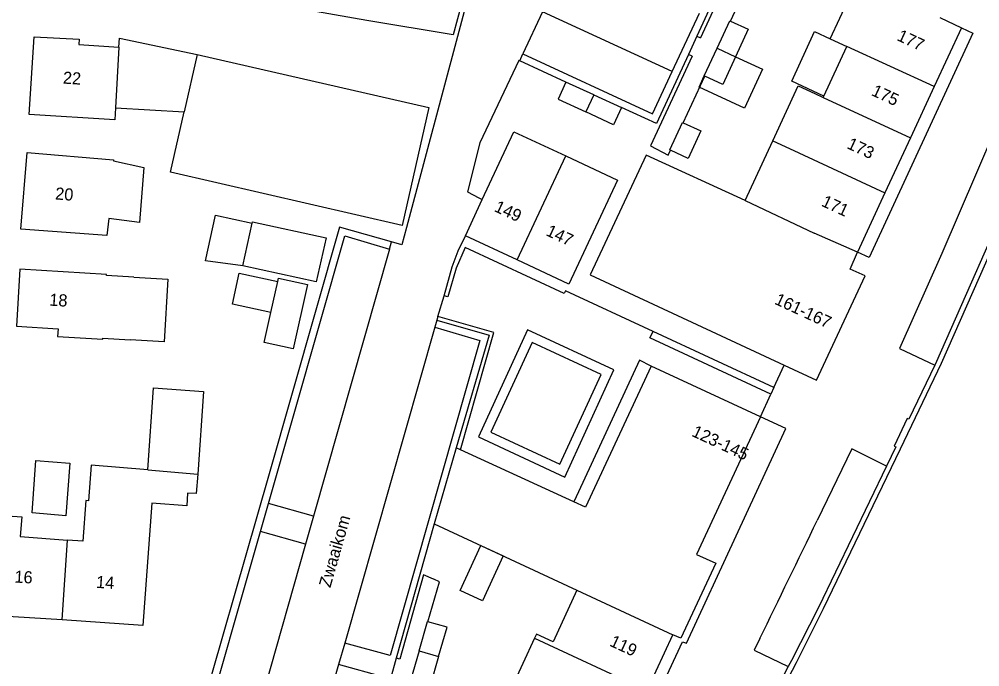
# Model space of a CAD drawing. Extents: x 194485 to 197793, y 468269 to 470822.
# Drawn here: x 194851.3 to 194946.2, y 470211.6 to 470275.6 of the extents above; entities that cross this region are included whole.
import ezdxf

# ---------------------------------------------------------------- set-up
doc = ezdxf.new("R2010")
doc.units = 0
for name, color, linetype in [('BGT grensvlak gebouwinstallatie plus 1', 7, 'Continuous'), ('BGT grensvlak pand op maaiveld', 7, 'Continuous'), ('BGT grensvlak pand op maaiveld LR', 7, 'Continuous'), ('BGT grensvlak scheiding', 7, 'Continuous'), ('BGT grensvlak wegdeel', 7, 'Continuous'), ('BGT tekst huisnummerreeks', 7, 'Continuous'), ('BGT tekst openbare ruimte label weg', 7, 'Continuous')]:
    doc.layers.add(name, color=color, linetype=linetype)

msp = doc.modelspace()

# ---------------------------------------------------------------- linework, layer by layer
at = {"layer": 'BGT grensvlak gebouwinstallatie plus 1'}
for p, q in [((194860.808, 470266.854), (194867.595, 470266.472)), ((194869.703, 470251.723), (194870.703, 470256.259)), ((194870.703, 470256.259), (194874.318, 470255.463)), ((194873.388, 470251.243), (194869.703, 470251.723)), ((194873.042, 470250.518), (194876.837, 470249.672))]:
    msp.add_line(p, q, dxfattribs=at)
for points in [[(194930.812, 470268.025), (194927.625, 470269.493), (194929.887, 470274.402), (194931.438, 470273.688)], [(194861.148, 470272.864), (194861.199, 470273.747), (194868.862, 470272.118)], [(194922.065, 470271.903), (194924.733, 470270.668), (194922.947, 470266.811), (194918.464, 470268.886), (194918.989, 470270.02)], [(194876.155, 470246.612), (194872.36, 470247.458), (194873.042, 470250.518)]]:
    msp.add_lwpolyline(points, dxfattribs=at)
at = {"layer": 'BGT grensvlak pand op maaiveld'}
for p, q in [((194931.438, 470273.688), (194934.004, 470279.214)), ((194942.256, 470275.78), (194944.402, 470274.782)), ((194944.402, 470274.782), (194941.707, 470268.957)), ((194931.438, 470273.688), (194933.074, 470272.934)), ((194861.148, 470272.864), (194860.808, 470266.854)), ((194918.989, 470270.02), (194920.25, 470272.743)), ((194930.812, 470268.025), (194933.074, 470272.934)), ((194868.862, 470272.118), (194867.595, 470266.472)), ((194919.041, 470269.996), (194918.989, 470270.02)), ((194908.059, 470268.146), (194905.311, 470269.41)), ((194941.707, 470268.957), (194939.366, 470263.896)), ((194908.059, 470268.146), (194910.808, 470266.882)), ((194929.906, 470268.275), (194930.747, 470267.883)), ((194930.747, 470267.883), (194930.812, 470268.025)), ((194939.366, 470263.896), (194936.84, 470258.46)), ((194923.027, 470257.7), (194925.758, 470263.599)), ((194936.84, 470258.46), (194934.118, 470252.604)), ((194895.377, 470254.214), (194897.05, 470257.795)), ((194873.388, 470251.243), (194874.318, 470255.463)), ((194900.489, 470251.825), (194895.377, 470254.214)), ((194933.387, 470250.922), (194934.118, 470252.604)), ((194862.633, 470250.119), (194865.979, 470249.918)), ((194865.979, 470249.918), (194865.606, 470243.729)), ((194876.155, 470246.612), (194876.837, 470249.672)), ((194876.837, 470249.672), (194876.914, 470250.016)), ((194876.914, 470250.016), (194879.763, 470249.381)), ((194865.606, 470243.729), (194862.26, 470243.931)), ((194924.534, 470236.323), (194913.749, 470241.323)), ((194894.911, 470233.039), (194894.464, 470233.245)), ((194906.094, 470227.892), (194894.911, 470233.039)), ((194892.303, 470225.729), (194906.407, 470219.175)), ((194913.33, 470209.262), (194915.883, 470214.767)), ((194902.22, 470214.416), (194899.695, 470208.973))]:
    msp.add_line(p, q, dxfattribs=at)
for points in [[(194865.832, 470284.517), (194865.905, 470284.975), (194895.891, 470280.446), (194894.183, 470274.089), (194885.65, 470275.505), (194865.543, 470279.058)], [(194920.25, 470272.743), (194921.51, 470275.465), (194921.562, 470275.441)], [(194921.562, 470275.441), (194923.325, 470274.625), (194922.065, 470271.903)], [(194860.808, 470266.854), (194860.741, 470265.675), (194852.278, 470266.214), (194852.759, 470273.887), (194857.213, 470273.632), (194857.177, 470273.123), (194861.148, 470272.864)], [(194868.862, 470272.118), (194891.752, 470266.876), (194889.117, 470255.209), (194866.252, 470260.49), (194867.595, 470266.472)], [(194922.065, 470271.903), (194920.804, 470269.18), (194919.041, 470269.996)], [(194905.311, 470269.41), (194904.533, 470267.719), (194907.281, 470266.455)], [(194925.758, 470263.599), (194928.26, 470269.033), (194929.906, 470268.275)], [(194910.808, 470266.882), (194910.03, 470265.191), (194907.281, 470266.455)], [(194915.645, 470262.661), (194915.574, 470262.694), (194916.834, 470265.416), (194916.905, 470265.383)], [(194916.905, 470265.383), (194918.649, 470264.576), (194917.389, 470261.854), (194915.645, 470262.661)], [(194897.05, 470257.795), (194900.183, 470264.499), (194905.296, 470262.11)], [(194851.461, 470254.875), (194852.069, 470262.435), (194860.597, 470261.731), (194860.598, 470261.629), (194863.61, 470260.952), (194863.162, 470255.537), (194860.132, 470255.915), (194859.95, 470254.235), (194851.461, 470254.875)], [(194905.296, 470262.11), (194910.408, 470259.721), (194905.602, 470249.436), (194900.489, 470251.825)], [(194923.027, 470257.7), (194913.229, 470262.188), (194907.699, 470250.347), (194926.885, 470241.431)], [(194874.318, 470255.463), (194874.345, 470255.586), (194881.63, 470254.01), (194880.648, 470249.655), (194873.388, 470251.243)], [(194862.633, 470250.119), (194859.928, 470250.282), (194859.934, 470250.392), (194851.35, 470250.91), (194851.01, 470245.27), (194855.133, 470245.021), (194855.086, 470244.253), (194859.548, 470243.984), (194859.555, 470244.094), (194862.26, 470243.931)], [(194926.885, 470241.431), (194930.09, 470239.941), (194934.867, 470250.242), (194933.387, 470250.922)], [(194879.763, 470249.381), (194878.347, 470243.028), (194875.498, 470243.663), (194876.155, 470246.612)], [(194913.749, 470241.323), (194907.249, 470227.361), (194906.094, 470227.892)], [(194863.997, 470231.05), (194864.57, 470239.167), (194869.507, 470238.818), (194868.929, 470230.637)], [(194924.534, 470236.323), (194918.216, 470222.708), (194920.13, 470221.83), (194916.66, 470214.413), (194915.883, 470214.767)], [(194894.464, 470233.245), (194892.296, 470225.732), (194892.303, 470225.729)], [(194852.929, 470231.974), (194856.296, 470231.72), (194855.904, 470226.529), (194852.563, 470226.821), (194852.929, 470231.974)], [(194863.997, 470231.05), (194858.392, 470231.52), (194858.143, 470227.996), (194857.863, 470228.032), (194857.592, 470223.998), (194856.065, 470224.117)], [(194868.929, 470230.637), (194868.793, 470228.71), (194867.935, 470228.771), (194867.846, 470227.518), (194864.411, 470227.76)], [(194864.411, 470227.76), (194863.502, 470215.673), (194855.535, 470216.228)], [(194855.535, 470216.228), (194847.428, 470216.73), (194847.923, 470224.098), (194848.114, 470224.099), (194848.24, 470226.644), (194851.549, 470226.407)], [(194851.549, 470226.407), (194851.393, 470224.485), (194856.065, 470224.117)], [(194899.12, 470222.559), (194897.085, 470218.118), (194894.87, 470219.137), (194896.904, 470223.575), (194899.12, 470222.559)], [(194906.407, 470219.175), (194904.056, 470214.062), (194902.41, 470214.826), (194902.22, 470214.416)], [(194890.798, 470213.154), (194891.623, 470216.055), (194891.67, 470216.042)], [(194892.738, 470212.603), (194893.563, 470215.504), (194891.67, 470216.042)], [(194890.798, 470213.154), (194889.972, 470210.253), (194890, 470210.245)], [(194892.738, 470212.603), (194891.912, 470209.702), (194890, 470210.245)]]:
    msp.add_lwpolyline(points, dxfattribs=at)
at = {"layer": 'BGT grensvlak pand op maaiveld LR'}
for p, q in [((194920.25, 470272.743), (194922.065, 470271.903)), ((194941.707, 470268.957), (194933.074, 470272.934)), ((194908.059, 470268.146), (194907.281, 470266.455)), ((194930.747, 470267.883), (194939.366, 470263.896)), ((194925.758, 470263.599), (194927.406, 470262.845)), ((194900.489, 470251.825), (194905.296, 470262.11)), ((194927.406, 470262.845), (194936.84, 470258.46)), ((194923.027, 470257.7), (194929.856, 470254.455)), ((194934.118, 470252.604), (194929.856, 470254.455)), ((194863.997, 470231.05), (194868.929, 470230.637)), ((194855.535, 470216.228), (194856.065, 470224.117)), ((194906.407, 470219.175), (194915.883, 470214.767)), ((194902.22, 470214.416), (194913.33, 470209.262)), ((194890.798, 470213.154), (194892.738, 470212.603))]:
    msp.add_line(p, q, dxfattribs=at)
at = {"layer": 'BGT grensvlak scheiding'}
for points in [[(194954.281, 470270.214), (194952.165, 470265.122), (194950.081, 470260.233), (194941.947, 470241.789), (194941.771, 470241.421)], [(194952.618, 470264.905), (194950.533, 470260.009), (194942.403, 470241.58), (194938.352, 470233.098), (194930.747, 470217.325), (194928.051, 470211.984), (194912.288, 470181.745), (194905.528, 470168.797), (194899.145, 470156.53), (194896.525, 470151.644), (194896.442, 470151.573), (194889.153, 470138.493), (194888.058, 470136.737), (194877.579, 470119.768), (194871.303, 470109.975), (194861.187, 470095.108), (194856.881, 470089.115), (194854.012, 470084.974)], [(194952.618, 470264.905), (194950.533, 470260.009), (194942.403, 470241.58), (194938.352, 470233.098), (194930.747, 470217.325), (194928.051, 470211.984), (194912.288, 470181.745), (194905.528, 470168.797), (194899.145, 470156.53), (194896.525, 470151.644), (194896.442, 470151.573), (194889.153, 470138.493), (194888.058, 470136.737), (194877.579, 470119.768), (194871.303, 470109.975), (194861.187, 470095.108), (194856.881, 470089.115), (194854.012, 470084.974)], [(194941.771, 470241.421), (194939.212, 470236.061), (194939.04, 470236.134), (194937.744, 470233.408), (194937.908, 470233.354), (194936.988, 470231.442)], [(194936.988, 470231.442), (194930.265, 470217.467), (194927.594, 470212.204), (194927.29, 470211.62)], [(194927.29, 470211.62), (194911.829, 470181.926), (194906.55, 470171.805), (194906.384, 470171.887), (194904.966, 470169.226), (194905.142, 470169.112), (194898.742, 470156.794), (194896.105, 470151.881), (194896.042, 470151.899), (194895.357, 470151.113), (194888.516, 470138.881), (194887.651, 470137.018), (194877.105, 470119.946), (194870.907, 470110.248), (194862.496, 470097.828), (194862.336, 470097.94), (194860.584, 470095.513), (194860.754, 470095.39), (194856.477, 470089.389), (194853.608, 470085.278)]]:
    msp.add_lwpolyline(points, dxfattribs=at)
at = {"layer": 'BGT grensvlak wegdeel'}
for p, q in [((194922.048, 470281.192), (194918.613, 470273.775)), ((194921.562, 470275.441), (194924.096, 470280.912)), ((194915.809, 470270.437), (194918.505, 470276.224)), ((194918.265, 470273.957), (194917.435, 470272.131)), ((194918.265, 470273.957), (194918.613, 470273.775)), ((194900.745, 470271.51), (194901.063, 470272.2)), ((194905.311, 470269.41), (194900.745, 470271.51)), ((194917.78, 470271.977), (194917.435, 470272.131)), ((194916.905, 470265.383), (194919.041, 470269.996)), ((194887.883, 470252.897), (194888.091, 470253.597)), ((194887.883, 470252.897), (194880.372, 470226.483)), ((194893.268, 470248.259), (194894.087, 470251.146)), ((194892.657, 470246.239), (194893.268, 470248.259)), ((194892.552, 470245.872), (194892.354, 470245.175)), ((194892.657, 470246.239), (194892.552, 470245.872)), ((194892.354, 470245.175), (194883.453, 470213.94)), ((194925.856, 470239.217), (194913.925, 470244.749)), ((194925.856, 470239.217), (194926.885, 470241.431)), ((194925.856, 470239.217), (194925.57, 470238.546)), ((194924.534, 470236.323), (194925.57, 470238.546)), ((194875.143, 470224.98), (194875.933, 470227.75)), ((194880.372, 470226.483), (194875.933, 470227.75)), ((194880.372, 470226.483), (194879.584, 470223.713)), ((194879.584, 470223.713), (194875.143, 470224.98)), ((194892.303, 470225.729), (194888.552, 470212.438)), ((194879.584, 470223.713), (194873.311, 470201.653)), ((194883.453, 470213.94), (194882.852, 470211.832)), ((194888.552, 470212.438), (194887.992, 470210.399))]:
    msp.add_line(p, q, dxfattribs=at)
for points in [[(194901.19, 470290.331), (194921.459, 470280.906), (194918.265, 470273.957)], [(194897.793, 470285.854), (194897.445, 470284.543), (194897.099, 470284.633), (194896.277, 470281.333), (194896.55, 470281.244), (194889.576, 470255.028)], [(194915.809, 470270.437), (194902.983, 470276.367), (194901.063, 470272.2)], [(194944.402, 470274.782), (194945.535, 470274.233), (194935.264, 470252.046), (194934.118, 470252.604)], [(194951.112, 470272.614), (194942.444, 470252.449), (194938.274, 470243.074), (194941.771, 470241.421)], [(194900.745, 470271.51), (194900.656, 470271.551), (194896.807, 470263.408), (194895.579, 470258.55), (194896.716, 470257.967), (194897.05, 470257.795)], [(194901.063, 470272.2), (194913.876, 470266.255), (194915.809, 470270.437)], [(194917.435, 470272.131), (194914.254, 470265.297), (194910.808, 470266.882)], [(194917.78, 470271.977), (194913.674, 470263.11), (194915.417, 470262.17), (194915.645, 470262.661)], [(194888.091, 470253.597), (194882.94, 470255.071), (194875.918, 470230.424), (194868.119, 470203.204), (194873.067, 470200.94)], [(194889.576, 470255.028), (194889.105, 470253.307), (194888.091, 470253.597)], [(194875.933, 470227.75), (194883.474, 470254.187), (194887.883, 470252.897)], [(194894.087, 470251.146), (194894.681, 470252.725), (194895.377, 470254.214)], [(194913.925, 470244.749), (194905.263, 470248.761), (194905.144, 470248.507), (194895.356, 470253.045), (194894.453, 470251.018)], [(194894.453, 470251.018), (194893.648, 470248.156), (194893.268, 470248.259)], [(194892.552, 470245.872), (194897.724, 470244.371), (194894.464, 470233.245)], [(194894.911, 470233.039), (194898.205, 470244.647), (194892.657, 470246.239)], [(194892.354, 470245.175), (194896.811, 470243.865), (194887.955, 470212.702), (194883.453, 470213.94)], [(194896.687, 470234.313), (194905.19, 470230.357), (194910.032, 470240.94), (194901.528, 470244.896), (194896.687, 470234.313)], [(194925.57, 470238.546), (194913.62, 470244.107), (194913.925, 470244.749)], [(194897.898, 470234.778), (194904.716, 470231.619), (194908.803, 470240.484), (194901.985, 470243.642), (194897.898, 470234.778)], [(194913.749, 470241.323), (194912.578, 470241.896), (194906.553, 470228.883), (194906.094, 470227.892)], [(194900.887, 470181.924), (194905.943, 470192.824), (194906.792, 470192.428), (194916.84, 470214.071), (194917.219, 470213.917), (194927.05, 470235.165), (194924.534, 470236.323)], [(194936.988, 470231.442), (194933.568, 470233.151), (194930.138, 470226.053)], [(194873.311, 470201.653), (194869.051, 470203.624), (194875.143, 470224.98)], [(194891.67, 470216.042), (194892.806, 470219.986), (194892.267, 470220.248), (194892.231, 470220.265), (194891.251, 470220.699), (194888.897, 470212.347), (194888.552, 470212.438)], [(194924.476, 470214.386), (194923.91, 470213.252), (194927.29, 470211.62)], [(194882.852, 470211.832), (194880.146, 470202.335), (194880.355, 470202.276)], [(194880.355, 470202.276), (194884.681, 470201.054), (194887.359, 470210.576), (194882.852, 470211.832)]]:
    msp.add_lwpolyline(points, dxfattribs=at)
msp.add_arc((185553.514, 474769.325), 10419.329, 334.0770252, 334.1483378, dxfattribs=at)

# ---------------------------------------------------------------- texts
at = {"layer": 'BGT tekst huisnummerreeks'}
for s, rotation, p in [('177', 335.2, (194937.938, 470273.575)), ('22', 356.4, (194855.587, 470269.257)), ('175', 335.2, (194935.416, 470268.134)), ('173', 335.1, (194932.99, 470262.892)), ('20', 355.4, (194854.815, 470257.807)), ('149', 335, (194898.14, 470256.674)), ('171', 335.1, (194930.471, 470257.198)), ('147', 335, (194903.253, 470254.285)), ('18', 356.6, (194854.244, 470247.303)), ('161-167', 335.1, (194925.843, 470247.508)), ('123-145', 335.1, (194917.66, 470234.441)), ('16', 356.5, (194850.8, 470219.927)), ('14', 356, (194858.865, 470219.405)), ('119', 335.1, (194909.547, 470213.7))]:
    msp.add_text(s, height=1.2, rotation=rotation, dxfattribs=at).set_placement(p)
at = {"layer": 'BGT tekst openbare ruimte label weg'}
msp.add_text('Zwaaikom', height=1.2, rotation=74.1, dxfattribs=at).set_placement((194882.033, 470219.349))

doc.saveas('drawing.dxf')
